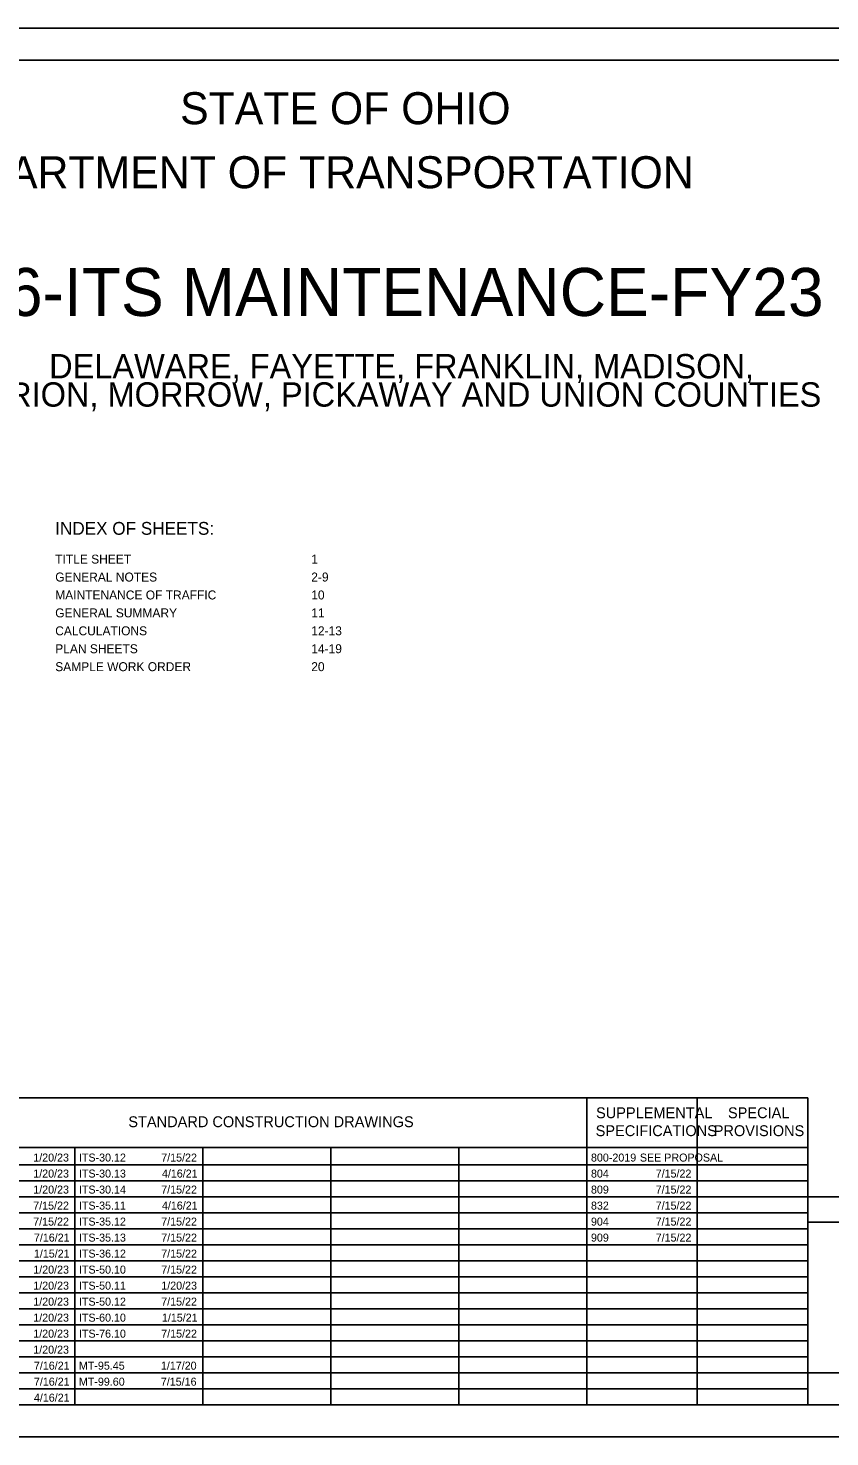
# Model space of a CAD drawing. Extents: x 0 to 34, y 0 to 22.
# Drawn here: x 11.42 to 23.95, y 0 to 22 of the extents above; entities that cross this region are included whole.
import ezdxf

# ---------------------------------------------------------------- set-up
doc = ezdxf.new("R2010")
doc.units = 0
for name, color, linetype in [('SH_Border', 7, 'Continuous'), ('SH_Cut_Line', 7, 'Continuous'), ('SH_Data', 7, 'Continuous'), ('SH_Text', 7, 'Continuous')]:
    doc.layers.add(name, color=color, linetype=linetype)

msp = doc.modelspace()

# ---------------------------------------------------------------- linework, layer by layer
at = {"layer": 'SH_Border'}
msp.add_lwpolyline([(1.5, 21.5), (33.5, 21.5), (33.5, 0.5), (1.5, 0.5)], close=True, dxfattribs=at)
at = {"layer": 'SH_Cut_Line'}
msp.add_lwpolyline([(0, 0), (34, 0), (34, 22), (0, 22)], close=True, dxfattribs=at)
at = {"layer": 'SH_Data'}
for p, q in [((10.15, 5.292), (23.6, 5.292)), ((20.15, 0.5), (20.15, 5.292)), ((21.875, 0.5), (21.875, 5.292)), ((23.6, 0.5), (23.6, 5.292)), ((10.15, 4.521), (23.6, 4.521)), ((12.15, 0.5), (12.15, 4.521)), ((14.15, 0.5), (14.15, 4.521)), ((16.15, 0.5), (16.15, 4.521)), ((18.15, 0.5), (18.15, 4.521)), ((10.15, 4.25), (23.6, 4.25)), ((10.15, 4), (23.6, 4)), ((10.15, 3.75), (23.6, 3.75)), ((23.6, 0.5), (23.6, 3.75)), ((23.6, 3.75), (26.4, 3.75)), ((10.15, 3.5), (23.6, 3.5)), ((23.6, 3.35), (26.4, 3.35)), ((10.15, 3.25), (23.6, 3.25)), ((10.15, 3), (23.6, 3)), ((10.15, 2.75), (23.6, 2.75)), ((10.15, 2.5), (23.6, 2.5)), ((10.15, 2.25), (23.6, 2.25)), ((10.15, 2), (23.6, 2)), ((10.15, 1.75), (23.6, 1.75)), ((10.15, 1.5), (23.6, 1.5)), ((10.15, 1.25), (23.6, 1.25)), ((10.15, 1), (23.6, 1)), ((10.15, 0.75), (23.6, 0.75)), ((23.6, 0.5), (26.4, 0.5))]:
    msp.add_line(p, q, dxfattribs=at)
msp.add_lwpolyline([(23.6, 0.5), (23.6, 1), (26.4, 1), (26.4, 0.5)], close=True, dxfattribs=at)

# ---------------------------------------------------------------- texts
at = {"layer": 'SH_Text'}
for s, height, p in [('STATE OF OHIO', 0.5, (13.795, 20.5)), ('DEPARTMENT OF TRANSPORTATION', 0.5, (9.747, 19.5)), ('D06-ITS MAINTENANCE-FY23', 0.75, (9.806, 17.505)), ('DELAWARE, FAYETTE, FRANKLIN, MADISON,', 0.38, (11.749, 16.531)), ('MARION, MORROW, PICKAWAY AND UNION COUNTIES', 0.38, (10.346, 16.089)), ('INDEX OF SHEETS:', 0.2, (11.844, 14.088)), ('TITLE SHEET', 0.14, (11.844, 13.638)), ('1', 0.14, (15.844, 13.638)), ('GENERAL NOTES', 0.14, (11.844, 13.358)), ('2-9', 0.14, (15.844, 13.358)), ('MAINTENANCE OF TRAFFIC', 0.14, (11.844, 13.078)), ('10', 0.14, (15.844, 13.078)), ('GENERAL SUMMARY', 0.14, (11.844, 12.798)), ('11', 0.14, (15.844, 12.798)), ('CALCULATIONS', 0.14, (11.844, 12.518)), ('12-13', 0.14, (15.844, 12.518)), ('PLAN SHEETS', 0.14, (11.844, 12.238)), ('14-19', 0.14, (15.844, 12.238)), ('SAMPLE WORK ORDER', 0.14, (11.844, 11.958)), ('20', 0.14, (15.844, 11.958)), ('SUPPLEMENTAL', 0.17, (20.293, 4.976)), ('SPECIAL', 0.17, (22.354, 4.976)), ('STANDARD CONSTRUCTION DRAWINGS', 0.17, (12.986, 4.836)), ('SPECIFICATIONS', 0.17, (20.287, 4.696)), ('PROVISIONS', 0.17, (22.132, 4.696)), ('1/20/23', 0.125, (11.501, 4.299)), ('ITS-30.12', 0.125, (12.214, 4.299)), ('7/15/22', 0.125, (13.5, 4.299)), ('800-2019', 0.125, (20.214, 4.299)), ('SEE PROPOSAL', 0.125, (20.978, 4.299)), ('1/20/23', 0.125, (11.501, 4.049)), ('4/16/21', 0.125, (13.511, 4.049)), ('7/15/22', 0.125, (21.225, 4.049)), ('ITS-30.13', 0.125, (12.214, 4.049)), ('804', 0.125, (20.214, 4.049)), ('1/20/23', 0.125, (11.501, 3.799)), ('ITS-30.14', 0.125, (12.214, 3.799)), ('7/15/22', 0.125, (13.5, 3.799)), ('809', 0.125, (20.214, 3.799)), ('7/15/22', 0.125, (21.225, 3.799)), ('7/15/22', 0.125, (11.5, 3.549)), ('ITS-35.11', 0.125, (12.214, 3.549)), ('4/16/21', 0.125, (13.511, 3.549)), ('832', 0.125, (20.214, 3.549)), ('7/15/22', 0.125, (21.225, 3.549)), ('7/15/22', 0.125, (11.5, 3.299)), ('ITS-35.12', 0.125, (12.214, 3.299)), ('7/15/22', 0.125, (13.5, 3.299)), ('904', 0.125, (20.214, 3.299)), ('7/15/22', 0.125, (21.225, 3.299)), ('7/16/21', 0.125, (11.511, 3.049)), ('ITS-35.13', 0.125, (12.214, 3.049)), ('7/15/22', 0.125, (13.5, 3.049)), ('909', 0.125, (20.214, 3.049)), ('7/15/22', 0.125, (21.225, 3.049)), ('1/15/21', 0.125, (11.511, 2.799)), ('ITS-36.12', 0.125, (12.214, 2.799)), ('7/15/22', 0.125, (13.5, 2.799)), ('1/20/23', 0.125, (11.501, 2.549)), ('ITS-50.10', 0.125, (12.214, 2.549)), ('7/15/22', 0.125, (13.5, 2.549)), ('1/20/23', 0.125, (11.501, 2.299)), ('ITS-50.11', 0.125, (12.214, 2.299)), ('1/20/23', 0.125, (13.501, 2.299)), ('1/20/23', 0.125, (11.501, 2.049)), ('ITS-50.12', 0.125, (12.214, 2.049)), ('7/15/22', 0.125, (13.5, 2.049)), ('1/20/23', 0.125, (11.501, 1.799)), ('ITS-60.10', 0.125, (12.214, 1.799)), ('1/15/21', 0.125, (13.511, 1.799)), ('1/20/23', 0.125, (11.501, 1.549)), ('ITS-76.10', 0.125, (12.214, 1.549)), ('7/15/22', 0.125, (13.5, 1.549)), ('1/20/23', 0.125, (11.501, 1.299)), ('7/16/21', 0.125, (11.511, 1.049)), ('MT-95.45', 0.125, (12.214, 1.049)), ('1/17/20', 0.125, (13.495, 1.049)), ('7/16/21', 0.125, (11.511, 0.799)), ('MT-99.60', 0.125, (12.214, 0.799)), ('7/15/16', 0.125, (13.494, 0.799)), ('4/16/21', 0.125, (11.511, 0.549))]:
    msp.add_text(s, height=height, dxfattribs=at).set_placement(p)

doc.saveas('drawing.dxf')
